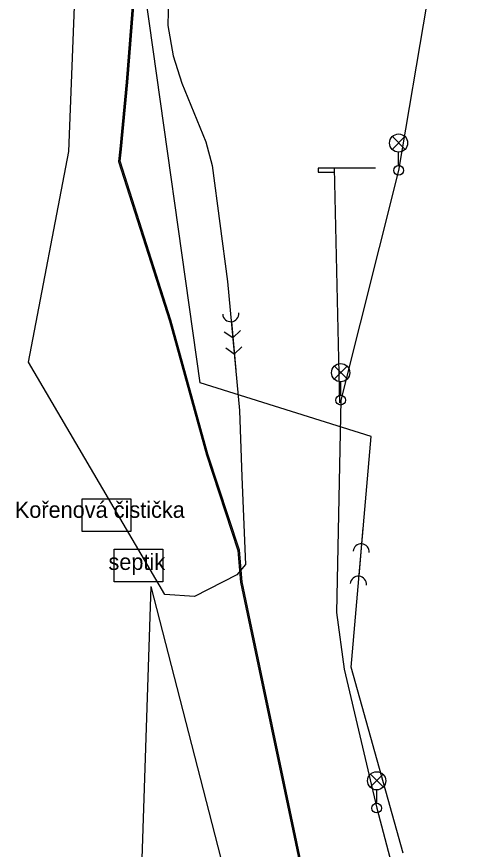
# Model space of a CAD drawing. Extents: x -880762 to -879575, y -1023083 to -1021277.
# Drawn here: x -880241.8 to -880186.7, y -1022739 to -1022636.5 of the extents above; entities that cross this region are included whole.
import ezdxf

# ---------------------------------------------------------------- set-up
doc = ezdxf.new("R2010")
doc.units = 0
for name, color, linetype in [('kanalizace trasa', 7, 'Continuous'), ('podzemní stavby', 7, 'Continuous'), ('vedeni NN VN', 7, 'Continuous'), ('VODOVOD', 7, 'Continuous'), ('znaky inž sítí ostatní', 7, 'Continuous')]:
    doc.layers.add(name, color=color, linetype=linetype)

msp = doc.modelspace()

# ---------------------------------------------------------------- linework, layer by layer
at = {"layer": 'kanalizace trasa'}
for p, q in [((-880235.32, -1022653.05), (-880232.74, -1022585.34)), ((-880219.14, -1022681.54), (-880232.74, -1022585.34)), ((-880222.99, -1022630.16), (-880223.12, -1022637.53)), ((-880223.12, -1022637.53), (-880222.49, -1022641.27)), ((-880222.49, -1022641.27), (-880221.41, -1022644.64)), ((-880221.41, -1022644.64), (-880218.43, -1022651.89)), ((-880218.43, -1022651.89), (-880217.65, -1022654.79)), ((-880240.33, -1022679.03), (-880235.32, -1022653.05)), ((-880217.65, -1022654.79), (-880215.75, -1022669.08)), ((-880215.75, -1022669.08), (-880214.28, -1022684.95)), ((-880215.28, -1022674.03), (-880214.75, -1022680)), ((-880215.1, -1022676.02), (-880216.17, -1022675.31)), ((-880214.18, -1022675.13), (-880215.1, -1022676.02)), ((-880215.02, -1022677.02), (-880215.02, -1022677.02)), ((-880223.48, -1022707.65), (-880240.33, -1022679.03)), ((-880198.06, -1022688.18), (-880219.14, -1022681.54)), ((-880214.28, -1022684.95), (-880213.99, -1022693.14)), ((-880200.51, -1022716.6), (-880198.06, -1022688.18)), ((-880213.99, -1022693.14), (-880213.55, -1022703.93)), ((-880199.54, -1022705.38), (-880199.03, -1022699.4)), ((-880199.28, -1022702.39), (-880199.28, -1022702.39)), ((-880213.55, -1022703.93), (-880214.6, -1022705.23)), ((-880214.6, -1022705.23), (-880219.85, -1022707.89)), ((-880229.25, -1022828.71), (-880225.18, -1022706.64)), ((-880198.58, -1022810.12), (-880225.18, -1022706.64)), ((-880219.85, -1022707.89), (-880223.48, -1022707.65)), ((-880194.09, -1022739.5), (-880200.51, -1022716.6))]:
    msp.add_line(p, q, dxfattribs=at)
msp.add_lwpolyline([(-880214, -1022677.13), (-880214.93, -1022678.01), (-880215.99, -1022677.3)], dxfattribs=at)
for centre, start, end in [((-880215.37, -1022673.03), 185.076, 5.076), ((-880199.28, -1022702.39), 355.0729, 175.0729), ((-880199.63, -1022706.38), 355.0729, 175.0729)]:
    msp.add_arc(centre, 1, start, end, dxfattribs=at)
at = {"layer": 'podzemní stavby'}
for points in [[(-880233.68, -1022695.86), (-880227.68, -1022695.86), (-880227.68, -1022699.86), (-880233.68, -1022699.86)], [(-880229.75, -1022702.06), (-880223.75, -1022702.06), (-880223.75, -1022706.06), (-880229.75, -1022706.06)]]:
    msp.add_lwpolyline(points, close=True, dxfattribs=at)
at = {"layer": 'vedeni NN VN'}
for p, q in [((-880191.2, -1022634.77), (-880194.67, -1022655.39)), ((-880201.92, -1022684.03), (-880202.57, -1022655.12)), ((-880197.52, -1022655.12), (-880202.52, -1022655.12)), ((-880194.67, -1022655.39), (-880201.81, -1022683.69)), ((-880201.81, -1022683.69), (-880202.34, -1022709.84)), ((-880202.34, -1022709.84), (-880201.37, -1022716.83)), ((-880201.37, -1022716.83), (-880197.37, -1022733.95)), ((-880197.37, -1022733.95), (-880186.68, -1022774.05))]:
    msp.add_line(p, q, dxfattribs=at)
msp.add_lwpolyline([(-880202.57, -1022655.12), (-880204.57, -1022655.12), (-880204.57, -1022655.62), (-880202.57, -1022655.62)], close=True, dxfattribs=at)
at = {"layer": 'VODOVOD'}
for p, q in [((-880228.08, -1022644.54), (-880227.11, -1022632.7)), ((-880227.32, -1022632.78), (-880228.28, -1022644.52)), ((-880228.28, -1022644.52), (-880229.04, -1022652.77)), ((-880228.84, -1022652.79), (-880228.08, -1022644.54)), ((-880229.04, -1022652.77), (-880229.22, -1022654.28)), ((-880229.02, -1022654.26), (-880228.84, -1022652.79)), ((-880229.22, -1022654.28), (-880222.93, -1022673.91)), ((-880222.74, -1022673.85), (-880229.02, -1022654.26)), ((-880222.93, -1022673.91), (-880218.37, -1022690.42)), ((-880218.18, -1022690.36), (-880222.74, -1022673.85)), ((-880218.37, -1022690.42), (-880214.48, -1022702.2)), ((-880214.28, -1022702.16), (-880218.18, -1022690.36)), ((-880214.48, -1022702.2), (-880214.16, -1022706.1)), ((-880213.96, -1022706.07), (-880214.28, -1022702.16)), ((-880214.16, -1022706.1), (-880204.85, -1022750.31)), ((-880204.65, -1022750.27), (-880213.96, -1022706.07))]:
    msp.add_line(p, q, dxfattribs=at)
at = {"layer": 'znaky inž sítí ostatní'}
for p, q in [((-880195.46, -1022652.8), (-880193.88, -1022651.22)), ((-880193.85, -1022652.8), (-880195.44, -1022651.21)), ((-880194.67, -1022654.79), (-880194.67, -1022653.14)), ((-880202.6, -1022681.1), (-880201.02, -1022679.52)), ((-880200.99, -1022681.09), (-880202.58, -1022679.51)), ((-880201.81, -1022683.09), (-880201.81, -1022681.44)), ((-880198.16, -1022731.36), (-880196.58, -1022729.78)), ((-880196.55, -1022731.35), (-880198.14, -1022729.77)), ((-880197.37, -1022733.35), (-880197.37, -1022731.7))]:
    msp.add_line(p, q, dxfattribs=at)
for centre, radius in [((-880194.67, -1022652.02), 1.12), ((-880194.67, -1022655.39), 0.6), ((-880201.81, -1022680.31), 1.12), ((-880201.81, -1022683.69), 0.6), ((-880197.37, -1022730.58), 1.12), ((-880197.37, -1022733.95), 0.6)]:
    msp.add_circle(centre, radius, dxfattribs=at)

# ---------------------------------------------------------------- texts
at = {"layer": 'podzemní stavby'}
for s, p in [('Kořenová čistička', (-880242, -1022698.19)), ('septik', (-880230.45, -1022704.61))]:
    msp.add_text(s, height=2, rotation=360, dxfattribs=at).set_placement(p)

doc.saveas('drawing.dxf')
